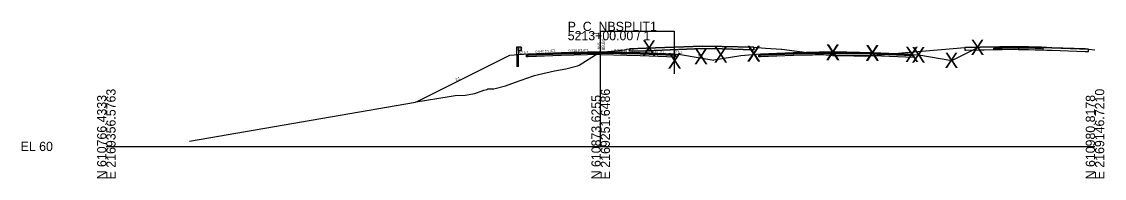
# Model space of a CAD drawing. Extents: x -26 to 1303, y -3010 to 12038.
# Drawn here: x 974.3 to 1302.8, y 7490.3 to 7537.8 of the extents above; entities that cross this region are included whole.
import ezdxf

# ---------------------------------------------------------------- set-up
doc = ezdxf.new("R2010")
doc.units = 0
for name, color, linetype in [('Default', 7, 'Continuous'), ('RD_GPK_XS_Cell', 7, 'Continuous'), ('RD_GPK_XS_Text_Node', 7, 'Continuous'), ('RD_PD_Final_TrvlWay', 7, 'Continuous'), ('RD_XS_Base', 7, 'Continuous'), ('RD_XS_ExGround', 7, 'Continuous'), ('RD_XS_ExPaveRet', 7, 'Continuous'), ('RD_XS_GR', 7, 'Continuous'), ('RD_XS_Greenside', 7, 'Continuous'), ('RD_XS_Pave', 7, 'Continuous'), ('RD_XS_PaveOvlay_CP', 7, 'Continuous'), ('RD_XS_TieSlope', 7, 'Continuous'), ('RD_XS_TX_Elev_EX', 7, 'Continuous'), ('RD_XS_TX_Elev_PR', 7, 'Continuous'), ('RD_XS_TX_ShdSlope', 7, 'Continuous'), ('RD_XS_TX_Slope', 7, 'Continuous')]:
    doc.layers.add(name, color=color, linetype=linetype)

msp = doc.modelspace()

# ---------------------------------------------------------------- linework, layer by layer
at = {"layer": 'Default'}
msp.add_lwpolyline([(1150, 7535), (1172.27, 7535), (1172.27, 7522.03)], dxfattribs=at)
at = {"layer": 'RD_GPK_XS_Cell'}
for p, q in [((1150, 7500), (1150, 7535)), ((1000, 7500), (1150, 7500)), ((1150, 7500), (1300, 7500))]:
    msp.add_line(p, q, dxfattribs=at)
at = {"layer": 'RD_PD_Final_TrvlWay'}
for p, q in [((1125.11, 7527.77), (1124.61, 7527.73)), ((1124.61, 7527.73), (1124.61, 7524.17)), ((1125.11, 7524.17), (1125.11, 7527.77))]:
    msp.add_line(p, q, dxfattribs=at)
at = {"layer": 'RD_XS_Base'}
for p, q in [((1276.82, 7530.01), (1276.82, 7530.08)), ((1276.82, 7530.08), (1276.82, 7529.68)), ((1276.82, 7529.92), (1276.82, 7530.01)), ((1127.5, 7527.67), (1128, 7527.69)), ((1127.5, 7527.17), (1127.5, 7527.67)), ((1127.5, 7527.67), (1127.5, 7527.67)), ((1128, 7527.19), (1127.5, 7527.17)), ((1127.5, 7527.17), (1127.5, 7527.17)), ((1127.5, 7527.17), (1127.5, 7527.17)), ((1128, 7527.69), (1138, 7528.09)), ((1128, 7527.69), (1128, 7527.69)), ((1138, 7527.59), (1128, 7527.19)), ((1128, 7527.19), (1128, 7527.19)), ((1138, 7528.09), (1150, 7528.33)), ((1138, 7528.09), (1138, 7528.09)), ((1150, 7527.83), (1138, 7527.59)), ((1138, 7527.59), (1138, 7527.59)), ((1150, 7528.33), (1150, 7528.49)), ((1150, 7528.49), (1150, 7527.83)), ((1150, 7528.33), (1150, 7527.83)), ((1162, 7528.09), (1150, 7528.33)), ((1150, 7528.33), (1150, 7528.33)), ((1150, 7527.83), (1150, 7527.83)), ((1150, 7527.83), (1150, 7527.83)), ((1150, 7527.83), (1162, 7527.59)), ((1172.27, 7527.68), (1162, 7528.09)), ((1162, 7527.59), (1172.77, 7527.16)), ((1164, 7528.01), (1164, 7528.01)), ((1164, 7527.51), (1164, 7527.51)), ((1172.77, 7527.66), (1172.27, 7527.68)), ((1172.27, 7527.68), (1172.27, 7527.68)), ((1172.77, 7527.16), (1172.77, 7527.66)), ((1172.77, 7527.66), (1172.77, 7527.66)), ((1172.77, 7527.16), (1172.77, 7527.16)), ((1172.77, 7527.16), (1172.77, 7527.16)), ((1198.02, 7527.67), (1198.51, 7527.69)), ((1198.02, 7527.66), (1198.02, 7527.67)), ((1198.02, 7527.17), (1198.02, 7527.66)), ((1198.51, 7527.19), (1198.02, 7527.17)), ((1198.51, 7527.69), (1198.52, 7527.69)), ((1198.52, 7527.19), (1198.51, 7527.19)), ((1198.52, 7527.69), (1208.42, 7528.08)), ((1208.42, 7527.58), (1198.52, 7527.19)), ((1208.42, 7528.08), (1208.52, 7528.09)), ((1208.52, 7527.59), (1208.42, 7527.58)), ((1208.52, 7528.09), (1220.14, 7528.32)), ((1220.14, 7527.82), (1208.52, 7527.59)), ((1220.14, 7528.32), (1220.52, 7528.33)), ((1220.52, 7527.83), (1220.14, 7527.82)), ((1220.52, 7528.48), (1220.52, 7528.49)), ((1220.52, 7528.49), (1220.52, 7528.47)), ((1220.52, 7528.33), (1220.52, 7528.48)), ((1220.52, 7528.47), (1220.52, 7527.83)), ((1220.52, 7528.33), (1220.52, 7528.32)), ((1220.52, 7528.33), (1220.52, 7528.33)), ((1220.71, 7528.32), (1220.52, 7528.33)), ((1220.52, 7528.33), (1220.52, 7528.33)), ((1220.52, 7528.32), (1220.52, 7527.83)), ((1220.52, 7527.83), (1220.71, 7527.82)), ((1232.52, 7528.09), (1220.71, 7528.32)), ((1220.71, 7527.82), (1232.52, 7527.59)), ((1232.74, 7528.08), (1232.52, 7528.09)), ((1232.52, 7527.59), (1232.75, 7527.58)), ((1244.52, 7527.61), (1232.74, 7528.08)), ((1232.75, 7527.58), (1245.02, 7527.09)), ((1244.53, 7527.61), (1244.52, 7527.61)), ((1245.02, 7527.59), (1244.53, 7527.61)), ((1245.02, 7527.58), (1245.02, 7527.59)), ((1245.02, 7527.09), (1245.02, 7527.58)), ((1269.32, 7529.77), (1269.82, 7529.78)), ((1269.32, 7529.27), (1269.32, 7529.77)), ((1269.82, 7529.28), (1269.32, 7529.27)), ((1269.82, 7529.78), (1271.82, 7529.82)), ((1271.82, 7529.32), (1269.82, 7529.28)), ((1271.82, 7529.82), (1276.82, 7529.92)), ((1276.82, 7529.42), (1271.82, 7529.32)), ((1279.87, 7529.86), (1276.82, 7529.92)), ((1276.82, 7529.92), (1276.82, 7529.42)), ((1276.82, 7529.68), (1276.82, 7529.42)), ((1276.82, 7529.42), (1279.87, 7529.36)), ((1281.82, 7529.82), (1279.87, 7529.86)), ((1279.87, 7529.36), (1281.82, 7529.32)), ((1282.58, 7529.8), (1281.82, 7529.82)), ((1281.82, 7529.32), (1282.77, 7529.3)), ((1283.82, 7529.78), (1282.58, 7529.8)), ((1282.77, 7529.3), (1284.32, 7529.27)), ((1284.01, 7529.77), (1283.82, 7529.78)), ((1284.32, 7529.77), (1284.01, 7529.77)), ((1284.32, 7529.46), (1284.32, 7529.77)), ((1284.32, 7529.27), (1284.32, 7529.46))]:
    msp.add_line(p, q, dxfattribs=at)
at = {"layer": 'RD_XS_ExGround'}
msp.add_lwpolyline([(1025.24, 7501.62), (1093.77, 7513.43), (1093.99, 7513.47), (1094.03, 7513.47), (1104.08, 7515.16), (1105.81, 7515.48), (1108.86, 7515.54), (1111.84, 7516.05), (1114.51, 7517.08), (1115.43, 7517.31), (1115.77, 7517.43), (1117.55, 7517.49), (1121.12, 7518.36), (1124.2, 7519.5), (1129.27, 7521.26), (1129.94, 7521.49), (1131.16, 7521.78), (1136.02, 7522.92), (1139.44, 7523.49), (1142.94, 7524.45), (1143.48, 7524.67), (1149.2, 7528.26), (1152.05, 7528.81), (1157.51, 7529.34), (1157.91, 7529.5), (1158.79, 7529.59), (1163.86, 7529.79), (1180.87, 7530.45), (1186.91, 7530.3), (1196.49, 7530.08), (1200.03, 7529.84), (1204.83, 7529.5), (1204.85, 7529.5), (1204.97, 7529.49), (1212.67, 7528.5), (1218.4, 7527.79), (1220.4, 7527.55), (1226.82, 7527.47), (1230.4, 7527.4), (1235.06, 7527.82), (1242.52, 7528.44), (1243.24, 7528.5), (1245.11, 7528.66), (1260.54, 7529.96), (1265.2, 7530.07), (1275.58, 7530.28), (1286.88, 7529.93), (1298.02, 7529.54), (1300, 7529.33)], dxfattribs=at)
at = {"layer": 'RD_XS_ExPaveRet'}
for p, q in [((1180.87, 7530.45), (1163.86, 7529.79)), ((1266.36, 7530.09), (1265.2, 7530.07)), ((1275.58, 7530.28), (1266.36, 7530.09)), ((1285.4, 7529.98), (1275.58, 7530.28)), ((1298.02, 7529.54), (1296.99, 7529.58))]:
    msp.add_line(p, q, dxfattribs=at)
for points in [[(1196.49, 7530.08), (1196.49, 7529.33), (1196.49, 7529.33), (1196.49, 7529.33), (1196.49, 7529.33), (1186.91, 7529.55), (1186.91, 7529.55), (1180.87, 7529.7), (1180.87, 7529.7), (1163.86, 7529.04), (1163.86, 7529.04), (1158.79, 7528.84), (1158.79, 7528.84), (1158.79, 7529.59), (1158.79, 7529.59), (1158.79, 7529.59), (1163.86, 7529.79), (1163.86, 7529.79), (1180.87, 7530.45), (1180.87, 7530.45), (1186.91, 7530.3), (1186.91, 7530.3), (1196.49, 7530.08), (1196.49, 7530.08), (1196.49, 7530.08)], [(1163.86, 7529.79), (1158.79, 7529.59), (1158.79, 7529.59), (1158.79, 7528.84), (1158.79, 7528.84), (1163.86, 7529.04), (1180.87, 7529.7), (1186.91, 7529.55), (1196.49, 7529.33), (1196.49, 7529.33), (1196.49, 7530.08), (1186.91, 7530.3), (1180.87, 7530.45)], [(1286.88, 7529.93), (1285.4, 7529.98), (1275.58, 7530.28), (1266.36, 7530.09), (1265.2, 7530.07), (1260.76, 7529.97), (1260.54, 7529.96), (1260.54, 7529.89), (1260.54, 7529.21), (1260.76, 7529.22), (1265.2, 7529.32), (1266.36, 7529.34), (1275.58, 7529.53), (1285.4, 7529.23), (1286.88, 7529.18), (1296.99, 7528.83), (1298.02, 7528.79), (1298.02, 7529.46), (1298.02, 7529.54), (1296.99, 7529.58), (1286.88, 7529.93)], [(1265.2, 7530.07), (1260.76, 7529.97), (1260.54, 7529.96)], [(1296.99, 7529.58), (1286.88, 7529.93), (1285.4, 7529.98)], [(1260.54, 7529.96), (1260.54, 7529.89), (1260.54, 7529.21), (1260.76, 7529.22), (1265.2, 7529.32), (1266.36, 7529.34), (1275.58, 7529.53), (1285.4, 7529.23), (1286.88, 7529.18), (1296.99, 7528.83), (1298.02, 7528.79), (1298.02, 7529.46), (1298.02, 7529.54)]]:
    msp.add_lwpolyline(points, dxfattribs=at)
at = {"layer": 'RD_XS_GR'}
for points in [[(1125.11, 7530.17), (1125.11, 7527.77), (1124.61, 7527.73), (1124.61, 7530.17), (1124.86, 7530.17), (1125.11, 7530.17)], [(1125.77, 7530.17), (1125.77, 7529), (1125.11, 7529), (1125.11, 7530.17), (1125.77, 7530.17)], [(1126.04, 7529.88), (1125.77, 7530.17), (1125.77, 7529), (1125.77, 7529), (1125.77, 7529), (1126.04, 7529.29), (1126.04, 7529.29), (1125.77, 7529.58), (1125.77, 7529.58), (1126.04, 7529.88), (1126.04, 7529.88)]]:
    msp.add_lwpolyline(points, dxfattribs=at)
at = {"layer": 'RD_XS_Greenside'}
for p, q in [((1256.52, 7526.1), (1264.42, 7530.05)), ((1122.29, 7527.55), (1094.2, 7513.5)), ((1174.27, 7527.83), (1184.32, 7526.16)), ((1192.52, 7527.52), (1184.32, 7526.16)), ((1246.52, 7527.76), (1256.52, 7526.1))]:
    msp.add_line(p, q, dxfattribs=at)
at = {"layer": 'RD_XS_Pave'}
for p, q in [((1270.65, 7530.11), (1269.82, 7530.1)), ((1269.82, 7530.1), (1269.82, 7530.03)), ((1269.82, 7530.03), (1269.82, 7529.94)), ((1271.82, 7529.98), (1269.82, 7529.94)), ((1271.82, 7530.14), (1270.65, 7530.11)), ((1270.65, 7529.95), (1271.82, 7529.98)), ((1274.8, 7530.2), (1271.82, 7530.14)), ((1276.82, 7530.08), (1271.82, 7529.98)), ((1271.82, 7529.98), (1274.8, 7530.04)), ((1276.82, 7530.24), (1274.8, 7530.2)), ((1274.8, 7530.04), (1276.82, 7530.08)), ((1279.87, 7530.18), (1276.82, 7530.24)), ((1276.82, 7530.08), (1279.87, 7530.02)), ((1281.82, 7529.98), (1276.82, 7530.08)), ((1276.82, 7530.08), (1276.82, 7529.92)), ((1276.82, 7529.92), (1276.82, 7530.08)), ((1281.82, 7530.14), (1279.87, 7530.18)), ((1279.87, 7530.02), (1281.82, 7529.98)), ((1282.58, 7530.12), (1281.82, 7530.14)), ((1281.82, 7529.98), (1282.58, 7529.96)), ((1283.82, 7529.94), (1281.82, 7529.98)), ((1283.82, 7530.1), (1282.58, 7530.12)), ((1283.82, 7530), (1283.82, 7530.1)), ((1283.82, 7529.94), (1283.82, 7530)), ((1138, 7528.4), (1128, 7528)), ((1138, 7528.24), (1128, 7527.85)), ((1128, 7527.85), (1138, 7528.24)), ((1128, 7527.69), (1138, 7528.09)), ((1128, 7528), (1128, 7528)), ((1128, 7528), (1128, 7527.85)), ((1128, 7527.85), (1128, 7527.85)), ((1128, 7527.85), (1128, 7527.69)), ((1128, 7527.85), (1128, 7527.85)), ((1128, 7527.85), (1128, 7527.85)), ((1128, 7527.69), (1128, 7527.69)), ((1128, 7527.69), (1128, 7527.69)), ((1150, 7528.64), (1138, 7528.4)), ((1150, 7528.49), (1138, 7528.24)), ((1138, 7528.24), (1150, 7528.49)), ((1138, 7528.4), (1138, 7528.4)), ((1138, 7528.09), (1150, 7528.33)), ((1138, 7528.24), (1138, 7528.24)), ((1138, 7528.24), (1138, 7528.24)), ((1138, 7528.09), (1138, 7528.09)), ((1162, 7528.4), (1150, 7528.64)), ((1150, 7528.33), (1150, 7528.49)), ((1150, 7528.49), (1162, 7528.24)), ((1162, 7528.24), (1150, 7528.49)), ((1150, 7528.49), (1150, 7528.33)), ((1150, 7528.33), (1150, 7528.33)), ((1150, 7528.33), (1150, 7528.33)), ((1150, 7528.33), (1162, 7528.09)), ((1172.27, 7527.99), (1162, 7528.4)), ((1162, 7528.24), (1172.27, 7527.83)), ((1172.27, 7527.83), (1162, 7528.24)), ((1162, 7528.09), (1172.27, 7527.68)), ((1164, 7528.32), (1164, 7528.32)), ((1164, 7528.16), (1164, 7528.16)), ((1164, 7528.16), (1164, 7528.16)), ((1164, 7528.01), (1164, 7528.01)), ((1172.27, 7527.83), (1172.27, 7527.99)), ((1172.27, 7527.99), (1172.27, 7527.99)), ((1172.27, 7527.83), (1172.27, 7527.83)), ((1172.27, 7527.83), (1172.27, 7527.83)), ((1172.27, 7527.68), (1172.27, 7527.83)), ((1172.27, 7527.83), (1172.27, 7527.83)), ((1172.27, 7527.68), (1172.27, 7527.68)), ((1172.27, 7527.68), (1172.27, 7527.68)), ((1208.42, 7528.4), (1198.52, 7528)), ((1208.42, 7528.24), (1198.52, 7527.85)), ((1198.52, 7527.85), (1208.42, 7528.24)), ((1198.52, 7527.69), (1208.42, 7528.08)), ((1198.52, 7528), (1198.52, 7528)), ((1198.52, 7528), (1198.52, 7527.85)), ((1198.52, 7527.85), (1198.52, 7527.84)), ((1198.52, 7527.84), (1198.52, 7527.69)), ((1208.52, 7528.4), (1208.42, 7528.4)), ((1208.52, 7528.25), (1208.42, 7528.24)), ((1208.42, 7528.24), (1208.52, 7528.25)), ((1208.42, 7528.08), (1208.52, 7528.09)), ((1220.14, 7528.64), (1208.52, 7528.4)), ((1220.14, 7528.48), (1208.52, 7528.25)), ((1208.52, 7528.25), (1220.14, 7528.48)), ((1208.52, 7528.09), (1220.14, 7528.32)), ((1220.52, 7528.64), (1220.14, 7528.64)), ((1220.52, 7528.49), (1220.14, 7528.48)), ((1220.14, 7528.48), (1220.52, 7528.49)), ((1220.14, 7528.32), (1220.52, 7528.33)), ((1220.71, 7528.64), (1220.52, 7528.64)), ((1220.52, 7528.48), (1220.52, 7528.49)), ((1220.52, 7528.49), (1220.71, 7528.48)), ((1220.71, 7528.48), (1220.52, 7528.49)), ((1220.52, 7528.49), (1220.52, 7528.49)), ((1220.52, 7528.49), (1220.52, 7528.49)), ((1220.52, 7528.49), (1220.52, 7528.48)), ((1220.52, 7528.33), (1220.52, 7528.48)), ((1220.52, 7528.48), (1220.52, 7528.33)), ((1220.52, 7528.33), (1220.52, 7528.33)), ((1220.52, 7528.33), (1220.52, 7528.33)), ((1220.52, 7528.33), (1220.71, 7528.32)), ((1232.52, 7528.4), (1220.71, 7528.64)), ((1220.71, 7528.48), (1232.52, 7528.25)), ((1232.52, 7528.25), (1220.71, 7528.48)), ((1220.71, 7528.32), (1232.52, 7528.09)), ((1232.74, 7528.4), (1232.52, 7528.4)), ((1232.52, 7528.25), (1232.74, 7528.24)), ((1232.74, 7528.24), (1232.52, 7528.25)), ((1232.52, 7528.09), (1232.74, 7528.08)), ((1244.52, 7527.92), (1232.74, 7528.4)), ((1232.74, 7528.24), (1244.52, 7527.77)), ((1244.52, 7527.77), (1232.74, 7528.24)), ((1232.74, 7528.08), (1244.52, 7527.61)), ((1244.52, 7527.77), (1244.52, 7527.92)), ((1244.52, 7527.92), (1244.52, 7527.92)), ((1244.52, 7527.76), (1244.52, 7527.77)), ((1244.52, 7527.61), (1244.52, 7527.76)), ((1269.82, 7529.94), (1270.65, 7529.95)), ((1269.82, 7529.94), (1269.82, 7529.78)), ((1269.82, 7529.78), (1271.82, 7529.82)), ((1271.82, 7529.82), (1276.82, 7529.92)), ((1276.82, 7529.92), (1281.82, 7529.82)), ((1281.82, 7529.82), (1283.82, 7529.78)), ((1282.58, 7529.96), (1283.82, 7529.94)), ((1283.82, 7529.78), (1283.82, 7529.94))]:
    msp.add_line(p, q, dxfattribs=at)
at = {"layer": 'RD_XS_PaveOvlay_CP'}
for p, q in [((1269.82, 7530.1), (1271.82, 7530.14)), ((1271.82, 7530.14), (1276.82, 7530.24)), ((1276.82, 7530.24), (1281.82, 7530.14)), ((1281.82, 7530.14), (1283.82, 7530.1)), ((1128, 7528), (1138, 7528.4)), ((1138, 7528.4), (1150, 7528.64)), ((1150, 7528.64), (1162, 7528.4)), ((1162, 7528.4), (1172.27, 7527.99)), ((1208.42, 7528.4), (1198.52, 7528)), ((1208.52, 7528.4), (1208.42, 7528.4)), ((1220.14, 7528.64), (1208.52, 7528.4)), ((1220.52, 7528.64), (1220.14, 7528.64)), ((1220.71, 7528.64), (1220.52, 7528.64)), ((1232.52, 7528.4), (1220.71, 7528.64)), ((1232.74, 7528.4), (1232.52, 7528.4)), ((1244.52, 7527.92), (1232.74, 7528.4))]:
    msp.add_line(p, q, dxfattribs=at)
at = {"layer": 'RD_XS_TieSlope'}
for p, q in [((1128, 7528), (1122.29, 7527.55)), ((1172.27, 7527.99), (1174.27, 7527.83)), ((1198.52, 7528), (1192.52, 7527.52)), ((1244.52, 7527.92), (1246.52, 7527.76))]:
    msp.add_line(p, q, dxfattribs=at)

# ---------------------------------------------------------------- texts
at = {"layer": 'RD_GPK_XS_Cell'}
for s, p in [('P_C_NBSPLIT1', (1140, 7535)), ('5213+00.00 / 1', (1140, 7532.2)), ('EL 60', (974, 7498.6))]:
    msp.add_text(s, height=2.8, dxfattribs=at).set_placement(p)
for s, p in [('E 2169356.5763', (1002.8, 7490)), ('E 2169251.6486', (1152.8, 7490)), ('E 2169146.7210', (1302.8, 7490)), ('N 610766.4333', (1000, 7490)), ('N 610873.6255', (1150, 7490)), ('N 610980.8178', (1300, 7490))]:
    msp.add_text(s, height=2.8, rotation=90, dxfattribs=at).set_placement(p)
at = {"layer": 'RD_GPK_XS_Text_Node'}
for p in [(1162.6, 7527.48), (1184.35, 7525.42), (1194.35, 7525.82), (1194.35, 7525.66), (1218.35, 7526.3), (1218.35, 7526.14), (1230.35, 7526.06), (1230.35, 7525.9), (1242.35, 7525.58), (1244.35, 7525.42), (1262.25, 7527.7), (1170.35, 7523.61), (1178.35, 7524.94), (1254.35, 7523.75)]:
    msp.add_text('X', height=4.69, dxfattribs=at).set_placement(p)
at = {"layer": 'RD_XS_TX_Elev_EX'}
msp.add_text('88.35', height=0.6, rotation=90, dxfattribs=at).set_placement((1149.73, 7529.5))
at = {"layer": 'RD_XS_TX_Elev_PR'}
msp.add_text('88.64', height=1, rotation=90, dxfattribs=at).set_placement((1151.3, 7529.14))
at = {"layer": 'RD_XS_TX_ShdSlope'}
for rotation, p in [(4.5739, (1125.26, 7527.98)), (355.4261, (1171.94, 7528.34))]:
    msp.add_text('12.5:1', height=0.75, rotation=rotation, dxfattribs=at).set_placement(p)
at = {"layer": 'RD_XS_TX_Slope'}
for s, rotation, p in [('0.040 FT./FT.', 2.2906, (1130.22, 7528.37)), ('0.020 FT./FT.', 1.1458, (1140.25, 7528.7)), ('0.020 FT./FT.', 358.8542, (1154.1, 7528.79)), ('0.040 FT./FT.', 357.7094, (1163.53, 7528.59)), ('6:1', 350.5377, (1179.4, 7527.41)), ('2:1', 26.5651, (1106.13, 7519.81))]:
    msp.add_text(s, height=0.75, rotation=rotation, dxfattribs=at).set_placement(p)

doc.saveas('drawing.dxf')
